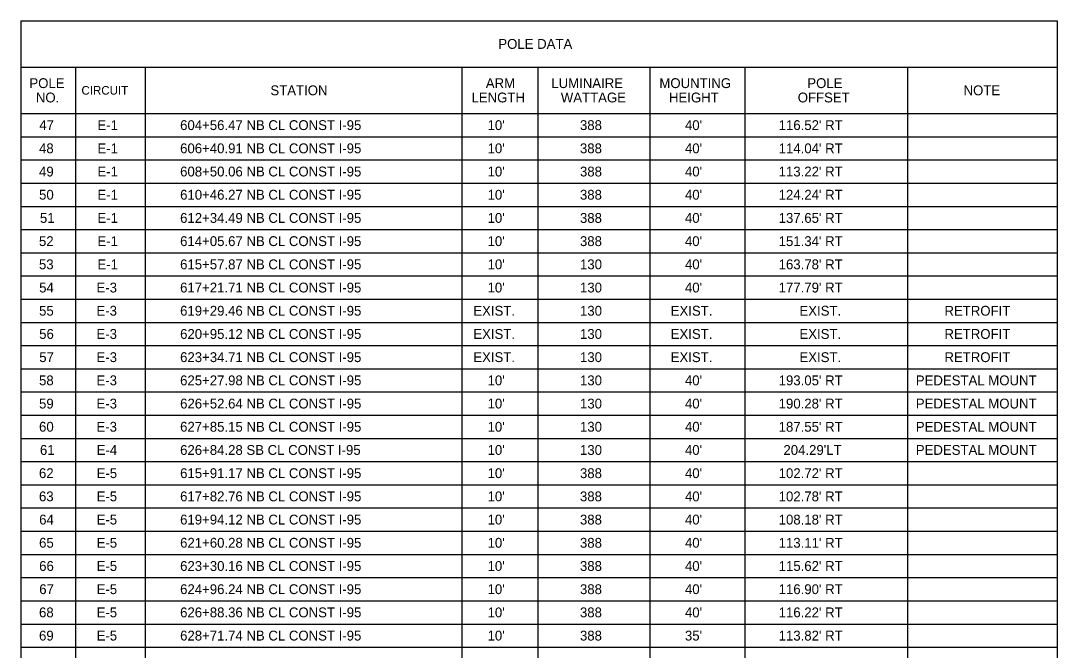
# Model space of a CAD drawing. Extents: x -818.1 to -802.4, y -2221.2 to -2187.7.
# Drawn here: x -809.73 to -802.37, y -2192.17 to -2187.69 of the extents above; entities that cross this region are included whole.
import ezdxf

# ---------------------------------------------------------------- set-up
doc = ezdxf.new("R2010")
doc.units = 0
for name, color, linetype in [('PlotBorder_dp', 7, 'Continuous'), ('SheetBorder_dp', 7, 'Continuous'), ('SheetLines_dp', 7, 'Continuous'), ('TextMinor', 7, 'Continuous')]:
    doc.layers.add(name, color=color, linetype=linetype)

msp = doc.modelspace()

# ---------------------------------------------------------------- linework, layer by layer
at = {"layer": 'PlotBorder_dp'}
for p, q in [((-809.3439, -2188.0217), (-809.3439, -2195.9417)), ((-809.3439, -2188.0217), (-809.3439, -2195.9417)), ((-808.8489, -2188.0217), (-808.8489, -2195.9417)), ((-808.8489, -2188.0217), (-808.8489, -2195.9417)), ((-806.5989, -2188.0217), (-806.5989, -2188.3517)), ((-806.5989, -2188.0217), (-806.5989, -2195.9417)), ((-806.0589, -2188.0217), (-806.0589, -2195.9417)), ((-806.0589, -2188.0217), (-806.0589, -2195.9417)), ((-805.2639, -2188.0217), (-805.2639, -2195.9417)), ((-805.2639, -2188.0217), (-805.2639, -2195.9417)), ((-804.5889, -2188.0217), (-804.5889, -2195.9417)), ((-804.5889, -2188.0217), (-804.5889, -2195.9417)), ((-803.4339, -2188.0217), (-803.4339, -2195.9417)), ((-803.4339, -2188.0217), (-803.4339, -2195.9417)), ((-809.7339, -2188.3517), (-802.3689, -2188.3517)), ((-808.8489, -2188.3517), (-806.5989, -2188.3517)), ((-806.5989, -2188.5167), (-806.5989, -2192.1467))]:
    msp.add_line(p, q, dxfattribs=at)
at = {"layer": 'SheetLines_dp'}
for p, q in [((-809.7339, -2187.6917), (-802.3689, -2187.6917)), ((-809.7339, -2187.6917), (-809.7339, -2195.9417)), ((-802.3689, -2187.6917), (-802.3689, -2195.9417)), ((-809.7339, -2188.0217), (-802.3689, -2188.0217)), ((-809.7339, -2188.0217), (-802.3689, -2188.0217))]:
    msp.add_line(p, q, dxfattribs=at)
at = {"layer": 'TextMinor'}
for p, q in [((-809.7339, -2188.3517), (-808.8489, -2188.3517)), ((-806.5989, -2188.3517), (-802.3689, -2188.3517)), ((-809.7339, -2188.5167), (-808.8489, -2188.5167)), ((-809.7339, -2188.5167), (-802.3689, -2188.5167)), ((-806.5989, -2188.5167), (-802.3689, -2188.5167)), ((-809.7339, -2188.6817), (-802.3689, -2188.6817)), ((-809.7339, -2188.6817), (-802.3689, -2188.6817)), ((-809.7339, -2188.8467), (-802.3689, -2188.8467)), ((-809.7339, -2188.8467), (-802.3689, -2188.8467)), ((-809.7339, -2189.0117), (-802.3689, -2189.0117)), ((-809.7339, -2189.0117), (-802.3689, -2189.0117)), ((-809.7339, -2189.1767), (-802.3689, -2189.1767)), ((-809.7339, -2189.1767), (-802.3689, -2189.1767)), ((-809.7339, -2189.3417), (-802.3689, -2189.3417)), ((-809.7339, -2189.3417), (-802.3689, -2189.3417)), ((-809.7339, -2189.5067), (-802.3689, -2189.5067)), ((-809.7339, -2189.5067), (-802.3689, -2189.5067)), ((-809.7339, -2189.6717), (-802.3689, -2189.6717)), ((-809.7339, -2189.6717), (-802.3689, -2189.6717)), ((-809.7339, -2189.8367), (-802.3689, -2189.8367)), ((-809.7339, -2189.8367), (-802.3689, -2189.8367)), ((-809.7339, -2190.0017), (-802.3689, -2190.0017)), ((-809.7339, -2190.0017), (-802.3689, -2190.0017)), ((-809.7339, -2190.1667), (-802.3689, -2190.1667)), ((-809.7339, -2190.1667), (-802.3689, -2190.1667)), ((-809.7339, -2190.3317), (-802.3689, -2190.3317)), ((-809.7339, -2190.3317), (-802.3689, -2190.3317)), ((-809.7339, -2190.4967), (-802.3689, -2190.4967)), ((-809.7339, -2190.4967), (-802.3689, -2190.4967)), ((-809.7339, -2190.6617), (-802.3689, -2190.6617)), ((-809.7339, -2190.6617), (-802.3689, -2190.6617)), ((-809.7339, -2190.8267), (-808.8489, -2190.8267)), ((-809.7339, -2190.8267), (-802.3689, -2190.8267)), ((-806.5989, -2190.8267), (-806.0589, -2190.8267)), ((-805.2639, -2190.8267), (-802.3689, -2190.8267)), ((-809.7339, -2190.9917), (-802.3689, -2190.9917)), ((-809.7339, -2190.9917), (-802.3689, -2190.9917)), ((-809.7339, -2191.1567), (-802.3689, -2191.1567)), ((-809.7339, -2191.1567), (-802.3689, -2191.1567)), ((-809.7339, -2191.3217), (-802.3689, -2191.3217)), ((-809.7339, -2191.3217), (-802.3689, -2191.3217)), ((-809.7339, -2191.4867), (-802.3689, -2191.4867)), ((-809.7339, -2191.4867), (-802.3689, -2191.4867)), ((-809.7339, -2191.6517), (-802.3689, -2191.6517)), ((-809.7339, -2191.6517), (-802.3689, -2191.6517)), ((-809.7339, -2191.8167), (-802.3689, -2191.8167)), ((-809.7339, -2191.8167), (-802.3689, -2191.8167)), ((-809.7339, -2191.9817), (-802.3689, -2191.9817)), ((-809.7339, -2191.9817), (-802.3689, -2191.9817)), ((-809.7339, -2192.1467), (-802.3689, -2192.1467)), ((-809.7339, -2192.1467), (-802.3689, -2192.1467))]:
    msp.add_line(p, q, dxfattribs=at)

# ---------------------------------------------------------------- texts
at = {"layer": 'SheetBorder_dp'}
for s, height, p in [('POLE DATA', 0.07, (-806.3403, -2187.8917)), ('POLE', 0.07, (-809.6722, -2188.1707)), ('ARM', 0.07, (-806.4294, -2188.1707)), ('LUMINAIRE', 0.07, (-805.964, -2188.1707)), ('MOUNTING', 0.07, (-805.1961, -2188.1707)), ('POLE', 0.07, (-804.1447, -2188.1707)), ('NO.', 0.07, (-809.6265, -2188.2727)), ('CIRCUIT', 0.06125, (-809.3023, -2188.2173)), ('STATION', 0.07, (-807.9597, -2188.2217)), ('LENGTH', 0.07, (-806.5308, -2188.2727)), ('WATTAGE', 0.07, (-805.8963, -2188.2727)), ('HEIGHT', 0.07, (-805.1279, -2188.2727)), ('OFFSET', 0.07, (-804.2129, -2188.2727)), ('NOTE', 0.07, (-803.0347, -2188.2217)), ('47', 0.07, (-809.6022, -2188.4692)), ('E-1', 0.07, (-809.1888, -2188.4692)), ('604+56.47 NB CL CONST I-95', 0.07, (-808.6013, -2188.4692)), ("10'", 0.07, (-806.4168, -2188.4692)), ('388', 0.07, (-805.7603, -2188.4692)), ("40'", 0.07, (-805.0143, -2188.4692)), ("116.52' RT", 0.07, (-804.3484, -2188.4692)), ('48', 0.07, (-809.6039, -2188.6342)), ('E-1', 0.07, (-809.1888, -2188.6342)), ('606+40.91 NB CL CONST I-95', 0.07, (-808.6013, -2188.6342)), ("10'", 0.07, (-806.4168, -2188.6342)), ('388', 0.07, (-805.7603, -2188.6342)), ("40'", 0.07, (-805.0143, -2188.6342)), ("114.04' RT", 0.07, (-804.3484, -2188.6342)), ('49', 0.07, (-809.6038, -2188.7992)), ('E-1', 0.07, (-809.1888, -2188.7992)), ('608+50.06 NB CL CONST I-95', 0.07, (-808.6013, -2188.7992)), ("10'", 0.07, (-806.4168, -2188.7992)), ('388', 0.07, (-805.7603, -2188.7992)), ("40'", 0.07, (-805.0143, -2188.7992)), ("113.22' RT", 0.07, (-804.3484, -2188.7992)), ('50', 0.07, (-809.6036, -2188.9642)), ('E-1', 0.07, (-809.1888, -2188.9642)), ('610+46.27 NB CL CONST I-95', 0.07, (-808.6013, -2188.9642)), ("10'", 0.07, (-806.4168, -2188.9642)), ('388', 0.07, (-805.7603, -2188.9642)), ("40'", 0.07, (-805.0143, -2188.9642)), ("124.24' RT", 0.07, (-804.3484, -2188.9642)), ('51', 0.07, (-809.5974, -2189.1292)), ('E-1', 0.07, (-809.1888, -2189.1292)), ('612+34.49 NB CL CONST I-95', 0.07, (-808.6013, -2189.1292)), ("10'", 0.07, (-806.4168, -2189.1292)), ('388', 0.07, (-805.7603, -2189.1292)), ("40'", 0.07, (-805.0143, -2189.1292)), ("137.65' RT", 0.07, (-804.3484, -2189.1292)), ('52', 0.07, (-809.6042, -2189.2942)), ('E-1', 0.07, (-809.1888, -2189.2942)), ('614+05.67 NB CL CONST I-95', 0.07, (-808.6013, -2189.2942)), ("10'", 0.07, (-806.4168, -2189.2942)), ('388', 0.07, (-805.7603, -2189.2942)), ("40'", 0.07, (-805.0143, -2189.2942)), ("151.34' RT", 0.07, (-804.3484, -2189.2942)), ('53', 0.07, (-809.6042, -2189.4592)), ('E-1', 0.07, (-809.1888, -2189.4592)), ('615+57.87 NB CL CONST I-95', 0.07, (-808.6013, -2189.4592)), ("10'", 0.07, (-806.4168, -2189.4592)), ('130', 0.07, (-805.76, -2189.4592)), ("40'", 0.07, (-805.0143, -2189.4592)), ("163.78' RT", 0.07, (-804.3484, -2189.4592)), ('54', 0.07, (-809.6028, -2189.6242)), ('E-3', 0.07, (-809.1956, -2189.6242)), ('617+21.71 NB CL CONST I-95', 0.07, (-808.6013, -2189.6242)), ("10'", 0.07, (-806.4168, -2189.6242)), ('130', 0.07, (-805.76, -2189.6242)), ("40'", 0.07, (-805.0143, -2189.6242)), ("177.79' RT", 0.07, (-804.3484, -2189.6242)), ('55', 0.07, (-809.6033, -2189.7892)), ('E-3', 0.07, (-809.1956, -2189.7892)), ('619+29.46 NB CL CONST I-95', 0.07, (-808.6013, -2189.7892)), ('EXIST.', 0.07, (-806.5182, -2189.7892)), ('130', 0.07, (-805.76, -2189.7892)), ('EXIST.', 0.07, (-805.1157, -2189.7892)), ('EXIST.', 0.07, (-804.2007, -2189.7892)), ('RETROFIT', 0.07, (-803.1706, -2189.7892)), ('56', 0.07, (-809.6028, -2189.9542)), ('E-3', 0.07, (-809.1956, -2189.9542)), ('620+95.12 NB CL CONST I-95', 0.07, (-808.6013, -2189.9542)), ('EXIST.', 0.07, (-806.5182, -2189.9542)), ('130', 0.07, (-805.76, -2189.9542)), ('EXIST.', 0.07, (-805.1157, -2189.9542)), ('EXIST.', 0.07, (-804.2007, -2189.9542)), ('RETROFIT', 0.07, (-803.1706, -2189.9542)), ('57', 0.07, (-809.6022, -2190.1192)), ('E-3', 0.07, (-809.1956, -2190.1192)), ('623+34.71 NB CL CONST I-95', 0.07, (-808.6013, -2190.1192)), ('EXIST.', 0.07, (-806.5182, -2190.1192)), ('130', 0.07, (-805.76, -2190.1192)), ('EXIST.', 0.07, (-805.1157, -2190.1192)), ('EXIST.', 0.07, (-804.2007, -2190.1192)), ('RETROFIT', 0.07, (-803.1706, -2190.1192)), ('58', 0.07, (-809.6039, -2190.2842)), ('E-3', 0.07, (-809.1956, -2190.2842)), ('625+27.98 NB CL CONST I-95', 0.07, (-808.6013, -2190.2842)), ("10'", 0.07, (-806.4168, -2190.2842)), ('130', 0.07, (-805.76, -2190.2842)), ("40'", 0.07, (-805.0143, -2190.2842)), ("193.05' RT", 0.07, (-804.3484, -2190.2842)), ('PEDESTAL MOUNT', 0.07, (-803.3739, -2190.2842)), ('59', 0.07, (-809.6038, -2190.4492)), ('E-3', 0.07, (-809.1956, -2190.4492)), ('626+52.64 NB CL CONST I-95', 0.07, (-808.6013, -2190.4492)), ("10'", 0.07, (-806.4168, -2190.4492)), ('130', 0.07, (-805.76, -2190.4492)), ("40'", 0.07, (-805.0143, -2190.4492)), ("190.28' RT", 0.07, (-804.3484, -2190.4492)), ('PEDESTAL MOUNT', 0.07, (-803.3739, -2190.4492)), ('60', 0.07, (-809.6036, -2190.6142)), ('E-3', 0.07, (-809.1956, -2190.6142)), ('627+85.15 NB CL CONST I-95', 0.07, (-808.6013, -2190.6142)), ("10'", 0.07, (-806.4168, -2190.6142)), ('130', 0.07, (-805.76, -2190.6142)), ("40'", 0.07, (-805.0143, -2190.6142)), ("187.55' RT", 0.07, (-804.3484, -2190.6142)), ('PEDESTAL MOUNT', 0.07, (-803.3739, -2190.6142)), ('61', 0.07, (-809.5974, -2190.7792)), ('E-4', 0.07, (-809.1942, -2190.7792)), ('626+84.28 SB CL CONST I-95', 0.07, (-808.6013, -2190.7792)), ("10'", 0.07, (-806.4168, -2190.7792)), ('130', 0.07, (-805.76, -2190.7792)), ("40'", 0.07, (-805.0143, -2190.7792)), ("204.29'LT", 0.07, (-804.3145, -2190.7792)), ('PEDESTAL MOUNT', 0.07, (-803.3739, -2190.7792)), ('62', 0.07, (-809.6042, -2190.9442)), ('E-5', 0.07, (-809.1947, -2190.9442)), ('615+91.17 NB CL CONST I-95', 0.07, (-808.6013, -2190.9442)), ("10'", 0.07, (-806.4168, -2190.9442)), ('388', 0.07, (-805.7603, -2190.9442)), ("40'", 0.07, (-805.0143, -2190.9442)), ("102.72' RT", 0.07, (-804.3484, -2190.9442)), ('63', 0.07, (-809.6042, -2191.1092)), ('E-5', 0.07, (-809.1947, -2191.1092)), ('617+82.76 NB CL CONST I-95', 0.07, (-808.6013, -2191.1092)), ("10'", 0.07, (-806.4168, -2191.1092)), ('388', 0.07, (-805.7603, -2191.1092)), ("40'", 0.07, (-805.0143, -2191.1092)), ("102.78' RT", 0.07, (-804.3484, -2191.1092)), ('64', 0.07, (-809.6028, -2191.2742)), ('E-5', 0.07, (-809.1947, -2191.2742)), ('619+94.12 NB CL CONST I-95', 0.07, (-808.6013, -2191.2742)), ("10'", 0.07, (-806.4168, -2191.2742)), ('388', 0.07, (-805.7603, -2191.2742)), ("40'", 0.07, (-805.0143, -2191.2742)), ("108.18' RT", 0.07, (-804.3484, -2191.2742)), ('65', 0.07, (-809.6033, -2191.4392)), ('E-5', 0.07, (-809.1947, -2191.4392)), ('621+60.28 NB CL CONST I-95', 0.07, (-808.6013, -2191.4392)), ("10'", 0.07, (-806.4168, -2191.4392)), ('388', 0.07, (-805.7603, -2191.4392)), ("40'", 0.07, (-805.0143, -2191.4392)), ("113.11' RT", 0.07, (-804.3484, -2191.4392)), ('66', 0.07, (-809.6028, -2191.6042)), ('E-5', 0.07, (-809.1947, -2191.6042)), ('623+30.16 NB CL CONST I-95', 0.07, (-808.6013, -2191.6042)), ("10'", 0.07, (-806.4168, -2191.6042)), ('388', 0.07, (-805.7603, -2191.6042)), ("40'", 0.07, (-805.0143, -2191.6042)), ("115.62' RT", 0.07, (-804.3484, -2191.6042)), ('67', 0.07, (-809.6022, -2191.7692)), ('E-5', 0.07, (-809.1947, -2191.7692)), ('624+96.24 NB CL CONST I-95', 0.07, (-808.6013, -2191.7692)), ("10'", 0.07, (-806.4168, -2191.7692)), ('388', 0.07, (-805.7603, -2191.7692)), ("40'", 0.07, (-805.0143, -2191.7692)), ("116.90' RT", 0.07, (-804.3484, -2191.7692)), ('68', 0.07, (-809.6039, -2191.9342)), ('E-5', 0.07, (-809.1947, -2191.9342)), ('626+88.36 NB CL CONST I-95', 0.07, (-808.6013, -2191.9342)), ("10'", 0.07, (-806.4168, -2191.9342)), ('388', 0.07, (-805.7603, -2191.9342)), ("40'", 0.07, (-805.0143, -2191.9342)), ("116.22' RT", 0.07, (-804.3484, -2191.9342)), ('69', 0.07, (-809.6038, -2192.0992)), ('E-5', 0.07, (-809.1947, -2192.0992)), ('628+71.74 NB CL CONST I-95', 0.07, (-808.6013, -2192.0992)), ("10'", 0.07, (-806.4168, -2192.0992)), ('388', 0.07, (-805.7603, -2192.0992)), ("35'", 0.07, (-805.0143, -2192.0992)), ("113.82' RT", 0.07, (-804.3484, -2192.0992))]:
    msp.add_text(s, height=height, dxfattribs=at).set_placement(p)

doc.saveas('drawing.dxf')
